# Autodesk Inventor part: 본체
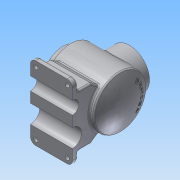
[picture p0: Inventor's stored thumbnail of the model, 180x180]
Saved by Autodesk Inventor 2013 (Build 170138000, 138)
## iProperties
Created: 2018-08
Part Number: 본체
Material: 알루미늄 6061
Document SubType Name: Modeling
Designer: user
Mass: 1872.73 g
Surface Area: 1087.55 cm^2
Volume: 691.045 cm^3
Density: 2.71 g/cm^3
Author: user
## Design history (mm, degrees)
sketch "스케치1"
  geometry: L1 (0, 0)-(0, 50); L2 (0, 50)-(96.671, 50); L3 (0, 0)-(108, 0); A1 r 116 centre (-8, 0) between (108, 0) and (96.671, 50)
  constraints: 6 end point, 2 point on circle, 1 centre point, 1 horizontal alignment, 1 parallel, 1 perpendicular, 1 vertical
  dimensions: "d4" = 108 distance of L1.start L3.end; "d5" = 116 radius of A1; "d6" = 100 diameter of L2 L3
revolve "회전1" sketch "스케치1" stored, may be unused: angle "d7" = 90 deg
node "작업 평면1"
sketch "스케치2"
  geometry: C1 r 38 at (0, 0); 1 further point
  constraints: 1 centre point, 1 coincident
  dimensions: "d9" = 76 diameter of C1
extrude "돌출1" join sketch "스케치2" stored distance "d10" = 10; taper "d11" = 0 deg
sketch "스케치3"
  geometry: L1 (-12, -38)-(-12, 38) reference; L2 (0, -38)-(0, 38) reference; L3 (96.671, -50)-(96.671, 50) reference; L4 (0, -50)-(0, 50) reference; L5 (96.671, -50)-(96.671, 50) reference; L6 (-12, 0)-(-12, 27); L7 (-12, 27)-(10, 27); L8 (10, 27)-(10, 40); L9 (-12, 0)-(98, 0); L10 (10, 40)-(90.163, 40); A1 r 116 centre (-8, 0) between (96.671, -50) and (96.671, 50) reference; A2 r 106 centre (-8, 0) between (98, 0) and (90.163, 40); 1 further point
  constraints: 10 end point, 3 perpendicular, 2 point on circle, 1 centre point, 1 midpoint, 1 parallel, 1 point on line
  dimensions: "d12" = 54 diameter of L7 L9; "d15" = 10 radial gap between concentric circles of A2 A1; "d16" = 80 diameter of L10 L9; "d17" = 22 distance of L6.end L7.end
revolve "회전2" sketch "스케치3" stored, may be unused: angle "d18" = 90 deg
node "작업 평면2"
sketch "스케치4"
  geometry: L1 (0, 50)-(0, -50) reference; L2 (0, 50)-(-96.671, 50) reference; L3 (-96.671, 50)-(-96.671, -50) reference; C1 r 38 at (-50, 0); 2 further points
  constraints: 1 centre point, 1 horizontal alignment, 1 midpoint
  dimensions: "d22" = 76 diameter of C1; "d23" = 50 distance from line of C1.centre L1
extrude "돌출2" join sketch "스케치4" stored distance "d24" = 10; taper "d25" = 0 deg
sketch "스케치5"
  geometry: C1 r 38 at (0, 0) reference; 2 further points
  constraints: 1 coincident
hole "구멍1" sketch "스케치5" at (0, 0) diameter "d26" = 54; stored, may be unused: countersink angle "d30" = 90 deg, drill point angle "d32" = 0 deg; dims "d27" = 6, "d28" = 4, "d29" = 2, "d31" = 50
sketch "스케치6"
  geometry: C1 r 27 at (0, 0) reference; 2 further points
  constraints: 1 vertical alignment
  dimensions: "d33" = 32.5 distance of point (0, 32.5) point (0, 0)
hole "구멍2" sketch "스케치6" at (0, 32.5) diameter "d34" = 3.242; stored, may be unused: countersink angle "d38" = 90 deg, drill point angle "d40" = 118 deg; dims "d35" = 8, "d36" = 4, "d37" = 2, "d39" = 10
sketch "스케치7"
  geometry: C1 r 27 at (0, 0) reference; 2 further points
  constraints: 1 vertical alignment
  dimensions: "d44" = 32.5 distance of point (0, 32.5) C1.centre
hole "구멍3" sketch "스케치7" at (0, 32.5) diameter "d45" = 3.242; stored, may be unused: countersink angle "d49" = 90 deg, drill point angle "d51" = 118 deg; dims "d46" = 8, "d47" = 4, "d48" = 2, "d50" = 10
fillet "모깎기1" dims "d55" = 3
node "작업 평면3"
sketch "스케치8"
  geometry: L1 (88, -70)-(8, -70); L2 (8, -70)-(8, 70); L3 (8, 70)-(88, 70); L4 (88, 70)-(88, -70); L5 (88, -70)-(8, 70); L6 (8, -70)-(88, 70); L7 (-12, -38)-(-12, 38) reference; L8 (0, -47)-(0, 47) reference; 3 further points
  constraints: 12 end point, 3 midpoint, 2 parallel, 1 horizontal, 1 horizontal alignment, 1 perpendicular
  dimensions: "d57" = 80 distance of L2.end L3.end; "d59" = 140 distance of L3.end L1.start; "d72" = 8 distance between parallel lines of L2 L8
extrude "돌출3" join sketch "스케치8" distance "d61" = 10; taper "d62" = 0 deg
fillet "모깎기2" dims "d63" = 10
sketch "스케치9"
  geometry: A1 r 10 centre (18, 60) between (18, 70) and (8, 60) reference; A2 r 10 centre (78, 60) between (88, 60) and (78, 70) reference; A3 r 10 centre (78, -60) between (78, -70) and (88, -60) reference; A4 r 10 centre (18, -60) between (8, -60) and (18, -70) reference; 5 further points
  constraints: 4 coincident
hole "구멍4" sketch "스케치9" at (18, 60), (78, 60), (78, -60), (18, -60) diameter "d64" = 8; stored, may be unused: countersink angle "d68" = 90 deg, drill point angle "d70" = 118 deg; dims "d65" = 8, "d66" = 4, "d67" = 2, "d69" = 10
node "작업 평면5"
  node "작업 평면4"
sketch "스케치10"
  geometry: L1 (-72.137, 50)-(-46.45, 50); L2 (-46.45, 50)-(-31.032, 39.204); L3 (-72.137, 0)-(-50, 0); L4 (-82, 70)-(-72, 70) reference; L5 (-72, 60)-(-72, -60) reference; L6 (-72.137, 50)-(-72.137, 0); A1 r 50 centre (0, 0) between (-50, 0) and (-31.032, 39.204) reference; A2 r 50 centre (0, 0) between (-31.032, 39.204) and (-50, 0); 2 further points
  constraints: 8 end point, 4 point on circle, 1 centre point, 1 concentric, 1 horizontal, 1 parallel, 1 point on line
  dimensions: "d75" = 35 deg angle of L2 L4; "d76" = 20 distance between parallel lines of L1 L4
extrude "돌출4" join sketch "스케치10" stored distance "d77" = 80; taper "d78" = 0 deg
sketch "스케치11"
  geometry: L1 (0, 10)-(10, 10) reference; L2 (0, 0)-(0, 10) reference; L3 (0, 0)-(120, 0) reference; L4 (120, 10)-(120, 0) reference; L5 (110, 10)-(120, 10) reference; L6 (110, 10)-(110, 35.55) reference; L7 (110, 35.55)-(99.204, 50.968) reference; L8 (10, 35.55)-(20.796, 50.968) reference; L9 (10, 10)-(10, 35.55) reference; C1 r 17.5 at (37.5, 0); C2 r 12.5 at (87.5, 0); A1 r 50 centre (60, 82) between (20.796, 50.968) and (99.204, 50.968) reference; 1 further point
  constraints: 2 centre point, 2 point on line
  dimensions: "d79" = 17.5 radius of C1; "d80" = 12.5 radius of C2; "d81" = 27.5 horizontal distance of C2.centre point (60, 82); "d82" = 22.5 horizontal distance of C1.centre point (60, 82)
extrude "돌출5" cut sketch "스케치11" stored distance "d83" = 80; taper "d84" = 0 deg
node "작업 평면6"
sketch "스케치12"
  geometry: C1 r 32.5 at (0, 0); 1 further point
  constraints: 1 centre point, 1 coincident, 1 other
  dimensions: "d86" = 65 diameter of C1
feature "엠보싱1" sketch "스케치12" dims "d4" = 108, "d5" = 116, "d6" = 100, "d87" = 0.5, "d88" = 0
chamfer "모따기1" distance "d89" = 1; stored, may be unused: second distance "d90" = 2, angle "d91" = 45 deg
fillet "모깎기4" dims "d92" = 3
fillet "모깎기5" dims "d93" = 3
fillet "모깎기6" dims "d94" = 3
fillet "모깎기7" dims "d95" = 3
node "솔리드1"
pattern_circular "원형 패턴1" dims angle "d42" = 360 deg
pattern_circular "원형 패턴2" dims angle "d53" = 360 deg
mirror "대칭1"
node "투영된 루프1"
node "투영된 루프2"
node "투영된 루프3"
node "투영된 루프4"
node "투영된 루프5"
node "투영된 루프6"
other parameters: "d8" = -12, "d19" = 65, "d56" = -82, "d73" = 8, "d85" = 135
